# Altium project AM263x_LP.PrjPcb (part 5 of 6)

## Sheet PROC111_XDS110_2.SchDoc: XDS110 JTAG/USB-to-UART Bridge
size 431 x 279 mm; Date: Not shown in title block; ApprovedBy: Not shown in title block; CheckedBy: Not shown in title block; Author: Not shown in title block; CompanyName: Not shown in title block; Engineer: Not shown in title block; Organization: Not shown in title block; Address1: Not shown in title block; Address2: Not shown in title block; Address3: Not shown in title block; Address4: Not shown in title block; DocumentNumber: 22; Revision: Use project parameter SCH_Rev; SheetNumber: 22; SheetTotal: 24; PageSetup: Record=PageOptions¦CenterHorizontal=True¦CenterVertical=True¦PrintScale=1.00¦XCorrection=1.00¦YCorrection=1.00¦PrintKind=0¦BorderSize=5000000¦LeftOffset=0¦BottomOffset=0¦Orientation=2¦PaperLength=1000¦PaperWidth=1000¦Scale=100¦PaperSource=15¦PrintQuality=600¦MediaType=1¦DitherType=10¦PaperKind=Letter¦PrintScaleMode=1
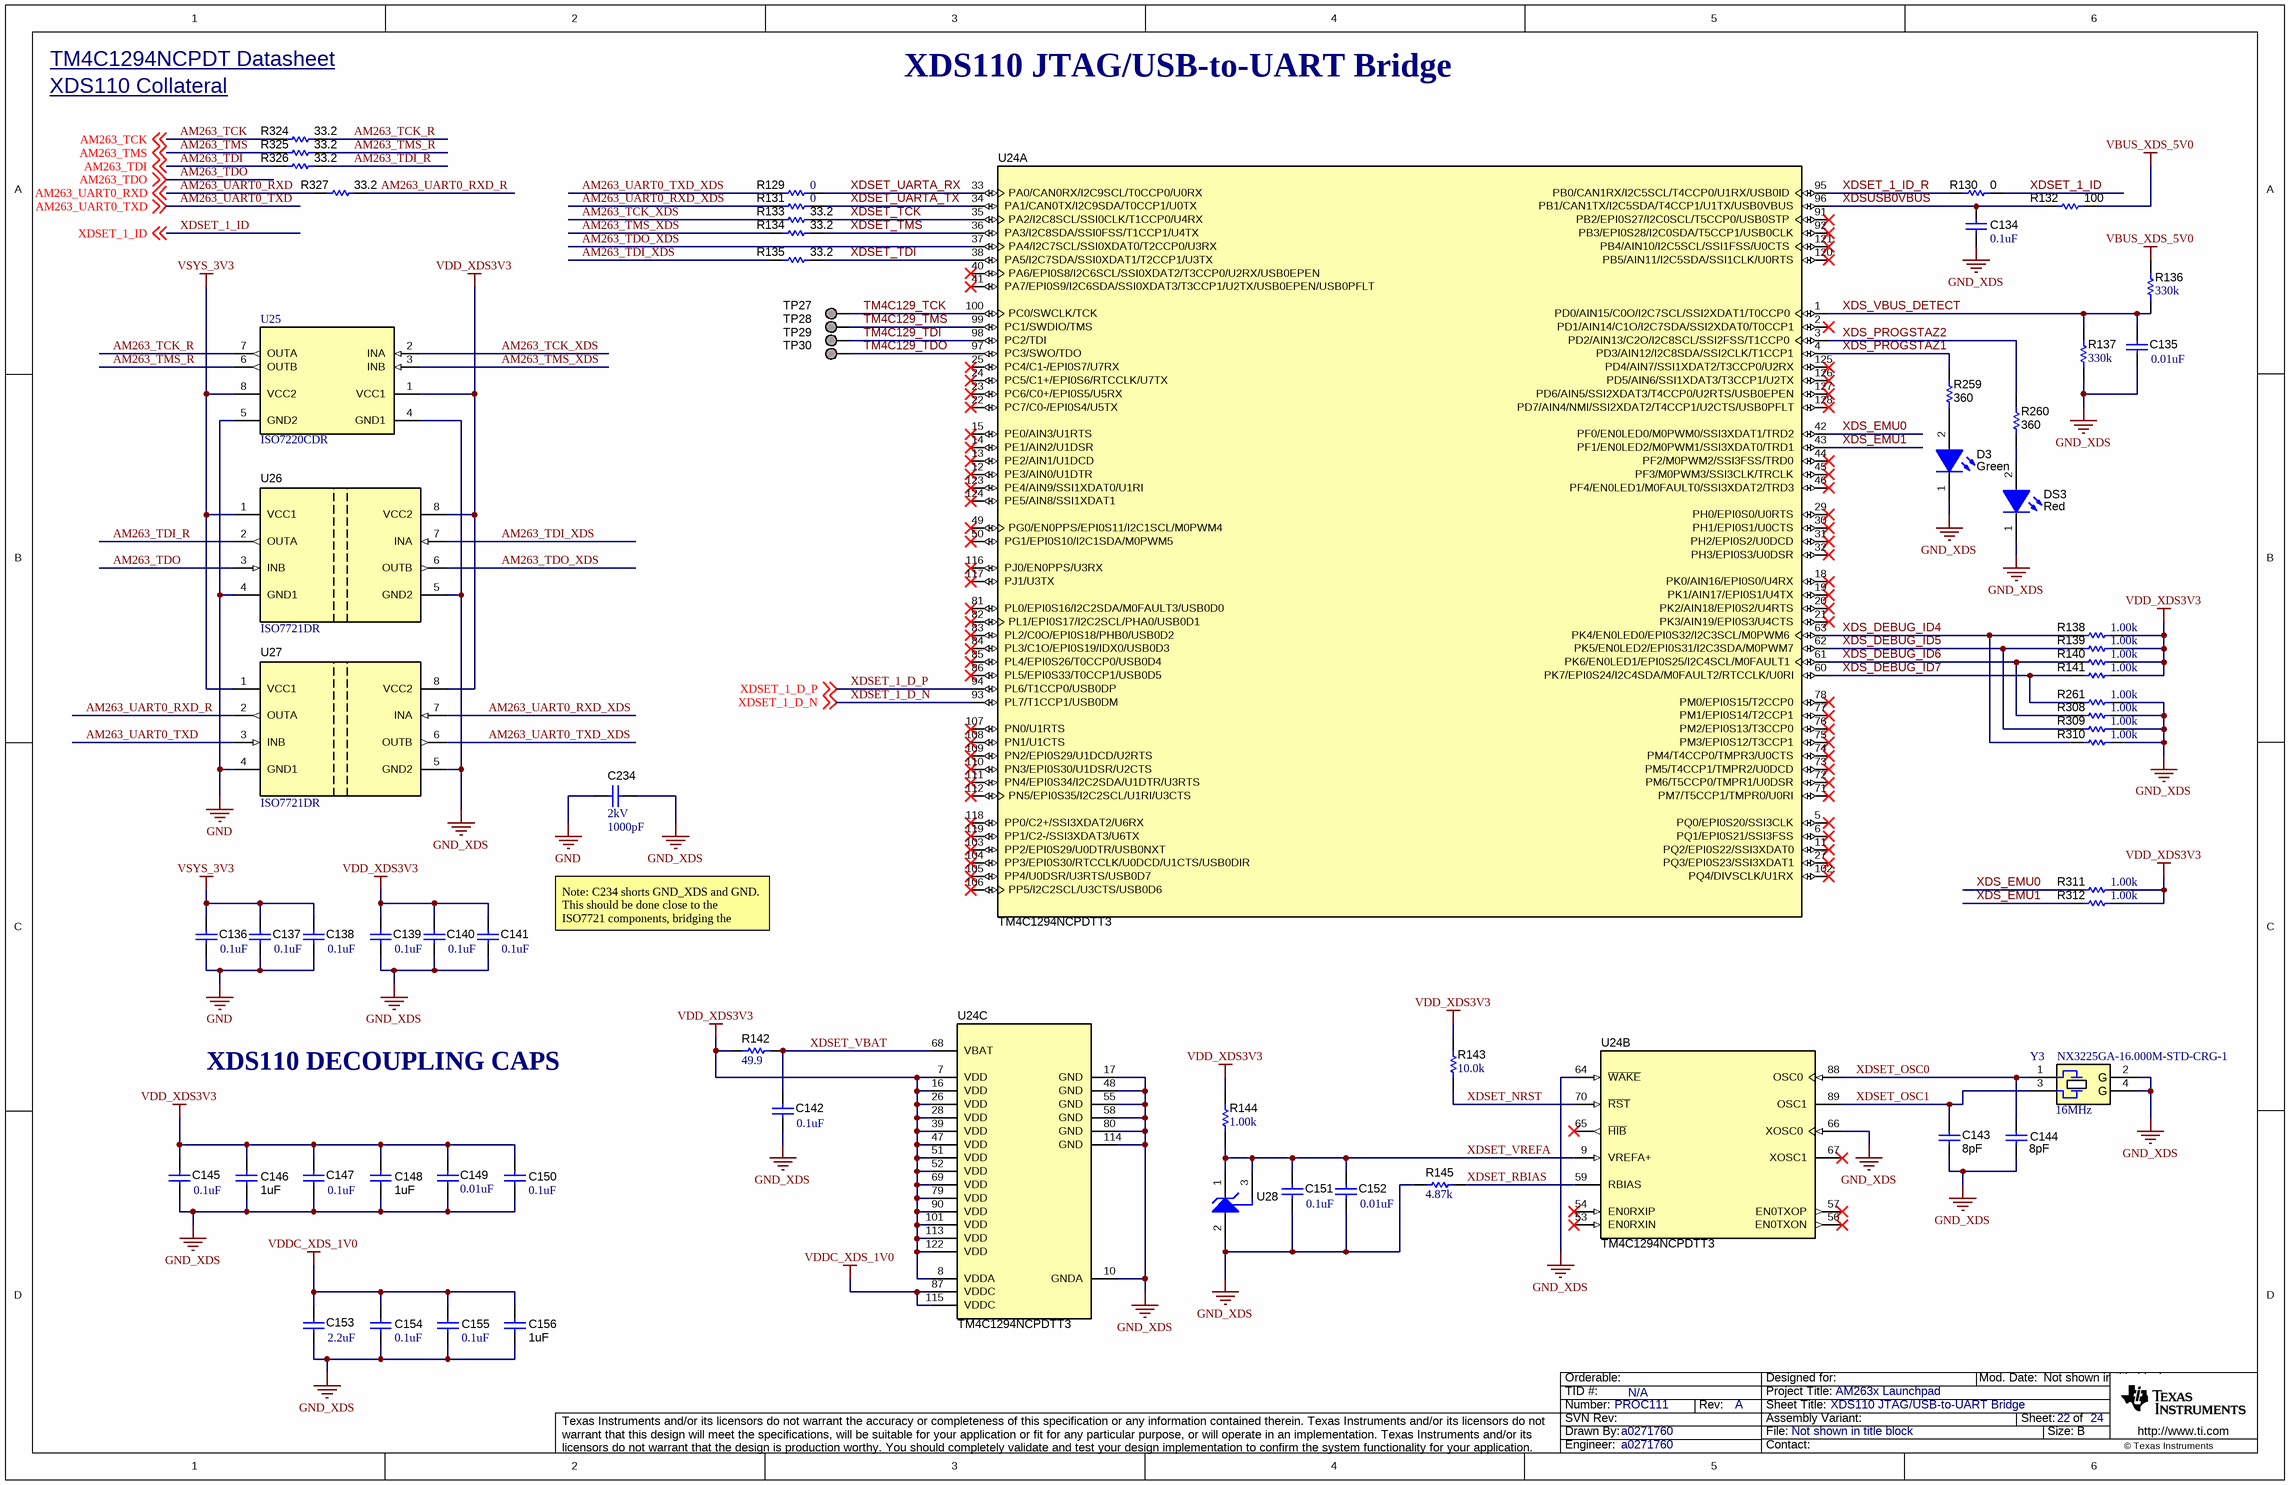
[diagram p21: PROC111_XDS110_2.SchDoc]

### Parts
C134  ValueDisplayed: 0.1uF  [0402]  (hidden comment: GRM155R71E104KE14D)
C135  ValueDisplayed: 0.01uF  [0402]  (hidden comment: GRM155R71E103KA01D)
C136  ValueDisplayed: 0.1uF  [0402]  (hidden comment: GRM155R71E104KE14D)
C137  ValueDisplayed: 0.1uF  [0402]  (hidden comment: GRM155R71E104KE14D)
C138  ValueDisplayed: 0.1uF  [0402]  (hidden comment: GRM155R71E104KE14D)
C139  ValueDisplayed: 0.1uF  [0402]  (hidden comment: GRM155R71E104KE14D)
C140  ValueDisplayed: 0.1uF  [0402]  (hidden comment: GRM155R71E104KE14D)
C141  ValueDisplayed: 0.1uF  [0402]  (hidden comment: GRM155R71E104KE14D)
C142  ValueDisplayed: 0.1uF  [0402]  (hidden comment: GRM155R71E104KE14D)
C143  Cap_F: 8pF  [0402]  (hidden comment: GCM1555C1H8R0DA16D)
C144  Cap_F: 8pF  [0402]  (hidden comment: GCM1555C1H8R0DA16D)
C145  ValueDisplayed: 0.1uF  [0402]  (hidden comment: GRM155R71E104KE14D)
C146  ValueDisplayed: 1uF  [0402_070]  (hidden comment: GCM155C71A105KE38D)
C147  ValueDisplayed: 0.1uF  [0402]  (hidden comment: GRM155R71E104KE14D)
C148  ValueDisplayed: 1uF  [0402_070]  (hidden comment: GCM155C71A105KE38D)
C149  ValueDisplayed: 0.01uF  [0402]  (hidden comment: GRM155R71E103KA01D)
C150  ValueDisplayed: 0.1uF  [0402]  (hidden comment: GRM155R71E104KE14D)
C151  ValueDisplayed: 0.1uF  [0402]  (hidden comment: GRM155R71E104KE14D)
C152  ValueDisplayed: 0.01uF  [0402]  (hidden comment: GRM155R71E103KA01D)
C153  ValueDisplayed: 2.2uF  [0402]  (hidden comment: GRM155C81C225KE11D)
C154  ValueDisplayed: 0.1uF  [0402]  (hidden comment: GRM155R71E104KE14D)
C155  ValueDisplayed: 0.1uF  [0402]  (hidden comment: GRM155R71E104KE14D)
C156  ValueDisplayed: 1uF  [0402_070]  (hidden comment: GCM155C71A105KE38D)
C234  VDC_V: 2kV  ValueDisplayed: 1000pF  [1808]  (hidden comment: GR442QR73D102KW01L)
D3  value Green  [WL-SMCW_GREEN]  (hidden comment: 150060VS75000)
DS3  value Red  [WL-SMCW_RED]  (hidden comment: 150060RS75000)
R129  ValueDisplayed: 0  [0402]  (hidden comment: ERJ-2GE0R00X)
R130  ValueDisplayed: 0  [0402L]  (hidden comment: ERJ-2GE0R00X)
R131  ValueDisplayed: 0  [0402]  (hidden comment: ERJ-2GE0R00X)
R132  ValueDisplayed: 100  [0402L]  (hidden comment: ERJ-2GEJ101X)
R133  ValueDisplayed: 33.2  [0402]  (hidden comment: CRCW040233R2FKED)
R134  ValueDisplayed: 33.2  [0402]  (hidden comment: CRCW040233R2FKED)
R135  ValueDisplayed: 33.2  [0402]  (hidden comment: CRCW040233R2FKED)
R136  ValueDisplayed: 330k  [0402L]  (hidden comment: CRCW0402330KFKED)
R137  ValueDisplayed: 330k  [0402L]  (hidden comment: CRCW0402330KFKED)
R138  ValueDisplayed: 1.00k  [0402L]  (hidden comment: CRCW04021K00FKED)
R139  ValueDisplayed: 1.00k  [0402L]  (hidden comment: CRCW04021K00FKED)
R140  ValueDisplayed: 1.00k  [0402L]  (hidden comment: CRCW04021K00FKED)
R141  ValueDisplayed: 1.00k  [0402L]  (hidden comment: CRCW04021K00FKED)
R142  ValueDisplayed: 49.9  [0402L]  (hidden comment: CRCW040249R9FKED)
R143  ValueDisplayed: 10.0k  [0402L]  (hidden comment: CRCW040210K0FKED)
R144  ValueDisplayed: 1.00k  [0402L]  (hidden comment: CRCW04021K00FKED)
R145  ValueDisplayed: 4.87k  [0402L]  (hidden comment: CRCW04024K87FKED)
R259  ValueDisplayed: 360  [0402L]  (hidden comment: ERJ-2GEJ361X)
R260  ValueDisplayed: 360  [0402L]  (hidden comment: ERJ-2GEJ361X)
R261  ValueDisplayed: 1.00k  [0402L]  (hidden comment: CRCW04021K00FKED)
R308  ValueDisplayed: 1.00k  [0402L]  (hidden comment: CRCW04021K00FKED)
R309  ValueDisplayed: 1.00k  [0402L]  (hidden comment: CRCW04021K00FKED)
R310  ValueDisplayed: 1.00k  [0402L]  (hidden comment: CRCW04021K00FKED)
R311  ValueDisplayed: 1.00k  [0402L]  (hidden comment: CRCW04021K00FKED)
R312  ValueDisplayed: 1.00k  [0402L]  (hidden comment: CRCW04021K00FKED)
R324  ValueDisplayed: 33.2  [0402]  (hidden comment: CRCW040233R2FKED)
R325  ValueDisplayed: 33.2  [0402]  (hidden comment: CRCW040233R2FKED)
R326  ValueDisplayed: 33.2  [0402]  (hidden comment: CRCW040233R2FKED)
R327  ValueDisplayed: 33.2  [0402]  (hidden comment: CRCW040233R2FKED)
TP27  TESTPOINT  [TP_25MIL-SMT]  (value not drawn)  (no BOM)
TP28  TESTPOINT  [TP_25MIL-SMT]  (value not drawn)  (no BOM)
TP29  TESTPOINT  [TP_25MIL-SMT]  (value not drawn)  (no BOM)
TP30  TESTPOINT  [TP_25MIL-SMT]  (value not drawn)  (no BOM)
U24  TM4C1294NCPDTT3  [PDT0128A]  (parts A,B,C of 3)
U25  ISO7220CDR  [D0008B_N]
U26  ISO7721DR  [D0008B_HV]
U27  ISO7721DR  [D0008B_HV]
U28  LM4040C25QDBZR  [DBZ0003A_N]  (value not drawn)
Y3  NX3225GA-16.000M-STD-CRG-1  Frequency_Fixed: 16MHz  [NDK_NX3225GA]

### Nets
GND: C136.1 C137.1 C138.1 C234.2 U25.5(GND2) U26.4(GND1) U27.4(GND1)
GND_XDS: C134.1 C135.1 C139.1 C140.1 C141.1 C142.2 C143.1 C144.1 C145.1 C146.2 C147.1 C148.2 C149.2 C150.1 C151.1 C152.1 C153.1 C154.1 C155.1 C156.2 C234.1 D3.1(K) DS3.1(K) R137.1 R145.1 R261.2 R308.2 R309.2 R310.2 U24.10(GNDA) U24.17(GND) U24.48(GND) U24.55(GND) U24.58(GND) U24.64(~{WAKE}) U24.66(XOSC0) U24.80(GND) U24.114(GND) U25.4(GND1) U26.5(GND2) U27.5(GND2) U28.2(ANODE) Y3.2(GND) Y3.4(GND)
VBUS_XDS_5V0: R132.2 R136.2
VDD_XDS3V3: C139.2 C140.2 C141.2 C145.2 C146.1 C147.2 C148.1 C149.1 C150.2 R138.2 R139.2 R140.2 R141.2 R142.2 R143.2 R144.2 R311.2 R312.2 U24.7(VDD) U24.8(VDDA) U24.16(VDD) U24.26(VDD) U24.28(VDD) U24.39(VDD) U24.47(VDD) U24.51(VDD) U24.52(VDD) U24.69(VDD) U24.79(VDD) U24.90(VDD) U24.101(VDD) U24.113(VDD) U24.122(VDD) U25.1(VCC1) U26.8(VCC2) U27.8(VCC2)
VDDC_XDS_1V0: C153.2 C154.2 C155.2 C156.1 U24.87(VDDC) U24.115(VDDC)
VSYS_3V3: C136.2 C137.2 C138.2 U25.8(VCC2) U26.1(VCC1) U27.1(VCC1)
AM263_TCK: R324.1 ; off-sheet AM263_TCK
AM263_TCK_R: R324.2 U25.7(OUTA)
AM263_TCK_XDS: R133.1 U25.2(INA)
AM263_TDI: R326.1 ; off-sheet AM263_TDI
AM263_TDI_R: R326.2 U26.2(OUTA)
AM263_TDI_XDS: R135.1 U26.7(INA)
AM263_TDO: U26.3(INB) ; off-sheet AM263_TDO
AM263_TDO_XDS: U24.37(PA4/I2C7SCL/SSI0XDAT0/T2CCP0/U3RX) U26.6(OUTB)
AM263_TMS: R325.1 ; off-sheet AM263_TMS
AM263_TMS_R: R325.2 U25.6(OUTB)
AM263_TMS_XDS: R134.1 U25.3(INB)
AM263_UART0_RXD: R327.1 ; off-sheet AM263_UART0_RXD
AM263_UART0_RXD_R: R327.2 U27.2(OUTA)
AM263_UART0_RXD_XDS: R131.1 U27.7(INA)
AM263_UART0_TXD: U27.3(INB) ; off-sheet AM263_UART0_TXD
AM263_UART0_TXD_XDS: R129.1 U27.6(OUTB)
TM4C129_TCK: TP27.1 U24.100(PC0/SWCLK/TCK)
TM4C129_TDI: TP29.1 U24.98(PC2/TDI)
TM4C129_TDO: TP30.1 U24.97(PC3/SWO/TDO)
TM4C129_TMS: TP28.1 U24.99(PC1/SWDIO/TMS)
XDS_DEBUG_ID4: R138.1 R310.1 U24.63(PK4/EN0LED0/EPI0S32/I2C3SCL/M0PWM6)
XDS_DEBUG_ID5: R139.1 R309.1 U24.62(PK5/EN0LED2/EPI0S31/I2C3SDA/M0PWM7)
XDS_DEBUG_ID6: R140.1 R308.1 U24.61(PK6/EN0LED1/EPI0S25/I2C4SCL/M0FAULT1)
XDS_DEBUG_ID7: R141.1 R261.1 U24.60(PK7/EPI0S24/I2C4SDA/M0FAULT2/RTCCLK/U0RI)
XDS_EMU0: R311.1 U24.42(PF0/EN0LED0/M0PWM0/SSI3XDAT1/TRD2)
XDS_EMU1: R312.1 U24.43(PF1/EN0LED2/M0PWM1/SSI3XDAT0/TRD1)
XDS_PROGSTAZ1: R259.2 U24.4(PD3/AIN12/I2C8SDA/SSI2CLK/T1CCP1)
XDS_PROGSTAZ2: R260.2 U24.3(PD2/AIN13/C2O/I2C8SCL/SSI2FSS/T1CCP0)
XDS_VBUS_DETECT: C135.2 R136.1 R137.2 U24.1(PD0/AIN15/C0O/I2C7SCL/SSI2XDAT1/T0CCP0)
XDSET_1_D_N: U24.93(PL7/T1CCP1/USB0DM) ; off-sheet XDSET_1_D_N
XDSET_1_D_P: U24.94(PL6/T1CCP0/USB0DP) ; off-sheet XDSET_1_D_P
XDSET_1_ID: R130.1 ; off-sheet XDSET_1_ID
XDSET_1_ID_R: R130.2 U24.95(PB0/CAN1RX/I2C5SCL/T4CCP0/U1RX/USB0ID)
XDSET_NRST: R143.1 U24.70(~{RST})
XDSET_OSC0: C144.2 U24.88(OSC0) Y3.1
XDSET_OSC1: C143.2 U24.89(OSC1) Y3.3
XDSET_RBIAS: R145.2 U24.59(RBIAS)
XDSET_TCK: R133.2 U24.35(PA2/I2C8SCL/SSI0CLK/T1CCP0/U4RX)
XDSET_TDI: R135.2 U24.38(PA5/I2C7SDA/SSI0XDAT1/T2CCP1/U3TX)
XDSET_TMS: R134.2 U24.36(PA3/I2C8SDA/SSI0FSS/T1CCP1/U4TX)
XDSET_UARTA_RX: R129.2 U24.33(PA0/CAN0RX/I2C9SCL/T0CCP0/U0RX)
XDSET_UARTA_TX: R131.2 U24.34(PA1/CAN0TX/I2C9SDA/T0CCP1/U0TX)
XDSET_VBAT: C142.1 R142.1 U24.68(VBAT)
XDSET_VREFA: C151.2 C152.2 R144.1 U24.9(VREFA+) U28.1(CATHODE) U28.3(NC)
XDSUSB0VBUS: C134.2 R132.1 U24.96(PB1/CAN1TX/I2C5SDA/T4CCP1/U1TX/USB0VBUS)
NetD3_2: D3.2(A) R259.1
NetDS3_2: DS3.2(A) R260.1

Not connected (* = marked no-connect by the designer): U24 2(PD1/AIN14/C1O/I2C7SDA/SSI2XDAT0/T0CCP1)* 5(PQ0/EPI0S20/SSI3CLK)* 6(PQ1/EPI0S21/SSI3FSS)* 11(PQ2/EPI0S22/SSI3XDAT0)* 12(PE3/AIN0/U1DTR)* 13(PE2/AIN1/U1DCD)* 14(PE1/AIN2/U1DSR)* 15(PE0/AIN3/U1RTS)* 18(PK0/AIN16/EPI0S0/U4RX)* 19(PK1/AIN17/EPI0S1/U4TX)* 20(PK2/AIN18/EPI0S2/U4RTS)* 21(PK3/AIN19/EPI0S3/U4CTS)* 22(PC7/C0-/EPI0S4/U5TX)* 23(PC6/C0+/EPI0S5/U5RX)* 24(PC5/C1+/EPI0S6/RTCCLK/U7TX)* 25(PC4/C1-/EPI0S7/U7RX)* 27(PQ3/EPI0S23/SSI3XDAT1)* 29(PH0/EPI0S0/U0RTS)* 30(PH1/EPI0S1/U0CTS)* 31(PH2/EPI0S2/U0DCD)* 32(PH3/EPI0S3/U0DSR)* 40(PA6/EPI0S8/I2C6SCL/SSI0XDAT2/T3CCP0/U2RX/USB0EPEN)* 41(PA7/EPI0S9/I2C6SDA/SSI0XDAT3/T3CCP1/U2TX/USB0EPEN/USB0PFLT)* 44(PF2/M0PWM2/SSI3FSS/TRD0)* 45(PF3/M0PWM3/SSI3CLK/TRCLK)* 46(PF4/EN0LED1/M0FAULT0/SSI3XDAT2/TRD3)* 49(PG0/EN0PPS/EPI0S11/I2C1SCL/M0PWM4)* 50(PG1/EPI0S10/I2C1SDA/M0PWM5)* 53(EN0RXIN)* 54(EN0RXIP)* 56(EN0TXON)* 57(EN0TXOP)* 65(~{HIB})* 67(XOSC1)* 71(PM7/T5CCP1/TMPR0/U0RI)* 72(PM6/T5CCP0/TMPR1/U0DSR)* 73(PM5/T4CCP1/TMPR2/U0DCD)* 74(PM4/T4CCP0/TMPR3/U0CTS)* 75(PM3/EPI0S12/T3CCP1)* 76(PM2/EPI0S13/T3CCP0)* 77(PM1/EPI0S14/T2CCP1)* 78(PM0/EPI0S15/T2CCP0)* 81(PL0/EPI0S16/I2C2SDA/M0FAULT3/USB0D0)* 82(PL1/EPI0S17/I2C2SCL/PHA0/USB0D1)* 83(PL2/C0O/EPI0S18/PHB0/USB0D2)* 84(PL3/C1O/EPI0S19/IDX0/USB0D3)* 85(PL4/EPI0S26/T0CCP0/USB0D4)* 86(PL5/EPI0S33/T0CCP1/USB0D5)* 91(PB2/EPI0S27/I2C0SCL/T5CCP0/USB0STP)* 92(PB3/EPI0S28/I2C0SDA/T5CCP1/USB0CLK)* 102(PQ4/DIVSCLK/U1RX)* 103(PP2/EPI0S29/U0DTR/USB0NXT)* 104(PP3/EPI0S30/RTCCLK/U0DCD/U1CTS/USB0DIR)* 105(PP4/U0DSR/U3RTS/USB0D7)* 106(PP5/I2C2SCL/U3CTS/USB0D6)* 107(PN0/U1RTS)* 108(PN1/U1CTS)* 109(PN2/EPI0S29/U1DCD/U2RTS)* 110(PN3/EPI0S30/U1DSR/U2CTS)* 111(PN4/EPI0S34/I2C2SDA/U1DTR/U3RTS)* 112(PN5/EPI0S35/I2C2SCL/U1RI/U3CTS)* 116(PJ0/EN0PPS/U3RX)* 117(PJ1/U3TX)* 118(PP0/C2+/SSI3XDAT2/U6RX)* 119(PP1/C2-/SSI3XDAT3/U6TX)* 120(PB5/AIN11/I2C5SDA/SSI1CLK/U0RTS)* 121(PB4/AIN10/I2C5SCL/SSI1FSS/U0CTS)* 123(PE4/AIN9/SSI1XDAT0/U1RI)* 124(PE5/AIN8/SSI1XDAT1)* 125(PD4/AIN7/SSI1XDAT2/T3CCP0/U2RX)* 126(PD5/AIN6/SSI1XDAT3/T3CCP1/U2TX)* 127(PD6/AIN5/SSI2XDAT3/T4CCP0/U2RTS/USB0EPEN)* 128(PD7/AIN4/NMI/SSI2XDAT2/T4CCP1/U2CTS/USB0PFLT)*

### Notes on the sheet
- XDS110 Collateral <https://software-dl.ti.com/ccs/esd/documents/xdsdebugprobes/emu_xds110.html>
- TM4C1294NCPDT Datasheet <http://www.ti.com/lit/ds/symlink/tm4c1294ncpdt.pdf>
- XDS110 JTAG/USB-to-UART Bridge
- Note: C234 shorts GND_XDS and GND. This should be done close to the ISO7721 components, bridging the air-gap between the two portions of the PCB
- XDS110 DECOUPLING CAPS

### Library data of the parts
C134 C136-C142 C145 C147 C150 C151 C154 C155 = CMP-0006659-2: CAP, CERM, 0.1 uF, 25 V, +/- 10%, X7R, 0402; Manufacturer: MuRata; TaMin_C: -55°C; Polarized: N; SizeAreaWB_mm2: 3; U/M: EA; Value: 0.1uF; TaMax_C: 125°C; SizeZ_mm: 0.6; SizeX_mm: 1; SizeY_mm: 0.5; Value2: 25V; Cap_F: 100nF; AEC Category: Q200; Value1: Unknown
C135 C149 C152 = CMP-0006658-2: CAP, CERM, 0.01 uF, 25 V, +/- 10%, X7R, 0402; Manufacturer: MuRata; TaMin_C: -55°C; Polarized: N; SizeAreaWB_mm2: 3; U/M: EA; Value: 0.01uF; TaMax_C: 125°C; SizeZ_mm: 0.6; SizeX_mm: 1; SizeY_mm: 0.5; Value2: 25V; Cap_F: 10nF; AEC Category: Q200; Value1: Unknown
C143 C144 = CMP-0087060-3: Cap Ceramic 8pF 50V C0G 0.5pF SMD 0402 125C Paper T/R; Manufacturer: Murata Electronics North America; TempCo: 30ppm/°C; AEC Qualified: Yes; AEC Grade: Grade 1; SizeZ_mm: 0.55mm
C146 C148 C156 = CMP-0006349-2: CAP, CERM, 1 uF, 10 V, +/- 10%, X7S, AEC-Q200 Grade 1, 0402; Manufacturer: MuRata; TaMin_C: -55°C; Polarized: N; SizeAreaWB_mm2: 3; Value1: Unknown; U/M: EA; Value: 1uF; TaMax_C: 125°C; SizeZ_mm: 0.7; SizeX_mm: 1; SizeY_mm: 0.5; Cap_Case: 0402; Value2: 10V; AEC Qualified: Y; Cap_F: 1µF; AEC Category: Q200
C153 = CMP-0006526-2: CAP, CERM, 2.2 uF, 16 V, +/- 10%, X6S, 0402; Manufacturer: MuRata; TaMin_C: -55°C; Polarized: N; SizeAreaWB_mm2: 3; Value1: Unknown; U/M: EA; Value: 2.2uF; TaMax_C: 105°C; SizeZ_mm: 0.6; SizeX_mm: 1; SizeY_mm: 0.5; Value2: 16V; Cap_F: 2.2µF; AEC Category: Q200
C234 = CMP-0009436-2: CAP, CERM, 1000 pF, 2000 V, +/- 10%, X7R, 1808; Manufacturer: MuRata; TaMin_C: -55°C; Polarized: N; SizeAreaWB_mm2: 16.5; Value1: Unknown; U/M: EA; Value: 1000pF; TaMax_C: 125°C; SizeZ_mm: 2.03; SizeX_mm: 4.5; SizeY_mm: 2; Value2: 2000V; SizeArea_mm2: 9; Cap_F: 1nF; AEC Category: Q200
D3 = CMP-0002894-2: LED, Green, SMD; Manufacturer: Wurth Elektronik; Io_A: 20mA; Value1: W; Vf_V: 2V; Type: AlInGaP
DS3 = CMP-0002947-3: LED, Red, SMD; Manufacturer: Wurth Elektronik; Value1: 0.072W; Vf_V: 2V; Angle: 140; Tjmax_C: 85°C; Type: AlInGaP; Vr_V: 5V; Io_A: 30mA; Power_TotalModule: 72mW
R129 R131 = CMP-0026992-3: RES, 0, 5%, 0.1 W, AEC-Q200 Grade 0, 0402; Manufacturer: Panasonic; Power_W: 100mW; TempCo: 600 ppm/C; Value_Code: 0000; Value: 0; EIA_Code: E24; SizeX_mm: 1; SizeY_mm: 0.5; SizeZ_mm: 0.6; Value2: 0.1W; CompType: Resistor; AEC Qualified: Y; VDC_V: 50V; AEC Category: Q200; SizeAreaWB_mm2: 3; INSTALLATION: DNP
R130 = CMP-0026992-3: RES, 0, 5%, 0.1 W, AEC-Q200 Grade 0, 0402; Manufacturer: Panasonic; Power_W: 100mW; TempCo: 600 ppm/C; Value_Code: 0000; Value: 0; EIA_Code: E24; SizeX_mm: 1; SizeY_mm: 0.5; SizeZ_mm: 0.6; Value2: 0.1W; AEC Qualified: Y; VDC_V: 50V; AEC Category: Q200; SizeAreaWB_mm2: 3
R132 = CMP-0026993-2: RES, 100, 5%, 0.1 W, AEC-Q200 Grade 0, 0402; Manufacturer: Panasonic; Power_W: 100mW; TempCo: 200 ppm/C; Value_Code: 100R; U/M: EA; Value: 100; EIA_Code: E24; SizeX_mm: 1; SizeY_mm: 0.5; SizeZ_mm: 0.6; Value2: 0.1W; AEC Qualified: Y; AEC Grade: 0; AEC Category: Q200
R133-R135 R324-R327 = CMP-0026299-2: RES, 33.2, 1%, 0.063 W, AEC-Q200 Grade 0, 0402; Manufacturer: Vishay-Dale; Power_W: 63mW; TempCo: 100 ppm/C; Value_Code: 33R2; Value: 33.2; EIA_Code: E96; SizeX_mm: 1; SizeY_mm: 0.5; SizeZ_mm: 0.6; Value2: 0.063W; AEC Qualified: Y; VDC_V: 50V; AEC Category: Q200; AEC Grade: 0
R136 R137 = CMP-0078210-2: RES, 330 k, 1%, 0.063 W, AEC-Q200 Grade 0, 0402; Manufacturer: Vishay-Dale; SizeArea_mm2: 0.5; AEC Qualified: Y; AEC Category: Q200; Value: 330k; SizeZ_mm: 0.6; TempCo: 100 ppm/C; AEC Grade: 0; Power_W: 63mW; VDC_V: 50V; Value2: 0.063W; SizeX_mm: 1
R138-R141 R144 R261 R308-R312 = CMP-0026071-3: RES, 1.00 k, 1%, 0.063 W, AEC-Q200 Grade 0, 0402; Manufacturer: Vishay-Dale; Power_W: 63mW; TempCo: 100 ppm/C; Value_Code: 1k00; Value: 1.00k; EIA_Code: E96; Res_ohm: 1k; SizeX_mm: 1; SizeY_mm: 0.5; SizeZ_mm: 0.6; Value2: 0.063W; AEC Qualified: Y; VDC_V: 50V; AEC Category: Q200; AEC Grade: 0
R142 = CMP-0026404-2: RES, 49.9, 1%, 0.063 W, AEC-Q200 Grade 0, 0402; Manufacturer: Vishay-Dale; Power_W: 63mW; TempCo: 100 ppm/C; Value_Code: 49R9; Value: 49.9; EIA_Code: E96; SizeX_mm: 1; SizeY_mm: 0.5; SizeZ_mm: 0.6; Value2: 0.063W; AEC Qualified: Y; VDC_V: 50V; AEC Category: Q200; AEC Grade: 0
R143 = CMP-0025958-3: RES, 10.0 k, 1%, 0.063 W, AEC-Q200 Grade 0, 0402; Manufacturer: Vishay-Dale; Power_W: 63mW; TempCo: 100 ppm/C; Value_Code: 10k0; Value: 10.0k; EIA_Code: E96; Res_ohm: 10k; SizeX_mm: 1; SizeY_mm: 0.5; SizeZ_mm: 0.6; Value2: 0.063W; AEC Qualified: Y; VDC_V: 50V; AEC Category: Q200; AEC Grade: 0
R145 = CMP-0026413-2: RES, 4.87 k, 1%, 0.063 W, AEC-Q200 Grade 0, 0402; Manufacturer: Vishay-Dale; Power_W: 63mW; TempCo: 100 ppm/C; Value_Code: 4k87; Value: 4.87k; EIA_Code: E96; SizeX_mm: 1; SizeY_mm: 0.5; SizeZ_mm: 0.6; Value2: 0.063W; AEC Qualified: Y; VDC_V: 50V; AEC Category: Q200; AEC Grade: 0
R259 R260 = CMP-0078194-1: RES, 360, 5%, 0.1 W, AEC-Q200 Grade 0, 0402; Manufacturer: Panasonic; Value_Code: 360R; SizeArea_mm2: 0.5; AEC Qualified: Y; AEC Category: Q200; Value: 360; SizeZ_mm: 0.6; EIA_Code: E24; TempCo: 200 ppm/C; AEC Grade: 0; Power_W: 100mW; VDC_V: 50V; Value2: 0.1W; U/M: EA; SizeX_mm: 1
TP27-TP30 = CMP-0078143-3: TEST POINT.  No entry in BOM.
U24 = CMP-0029856-2: Tiva C Series Microcontroller, 1024 KB Flash, 256 KB SRAM, 12 Bit, 20 Channels, -40 to 105 degC, 128-Pin TQFP (PDT), Green (RoHS & no Sb/Br), Tray; Manufacturer: Texas Instruments; ADC Channels: 20; CPU: ARM Cortex-M4; Flash: 1024 KB; ADC Resolution: 12 Bits; Max Speed: 120 MHz; SRAM: 256 KB; SizeAreaWB_mm2: 324.0; SizeArea_mm2: 256.0; SizeX_mm: 16.0; SizeZ_mm: 1.2; CompType: IC
U25 = CMP-0029369-1: 25 Mbps Dual Channels, 2 / 0, Digital Isolator, 3.3 V / 5 V, -40 to +125 degC, 8-pin SOIC (D), Green (RoHS & no Sb/Br); Manufacturer: Texas Instruments; Supply Voltage(s)(V): 3.3, 5; Prop Delay(Max)(ns): 42; Insulation Rating(VRMS): 2500; Datarate(Mbps): 25; TTL/CMOS Input Threshold: TTL; Rating: Catalog; Input Noise Filter: Yes
U26 U27 = CMP-0076059-2: High Speed, Robust EMC Dual-Channel Digital Isolator, D0008B (SOIC-8); Manufacturer: Texas Instruments; SizeY_mm: 4.9; SizeArea_mm2: 29.4; Rating: Catalog; CompType: IC; AEC Category: Q200; AEC Qualified: N; SizeZ_mm: 1.75; SizeAreaWB_mm2: 55.2; SizeX_mm: 6.0
U28 = CMP-0033001-1: Precision Micropower Shunt Voltage Reference, 0.5% accuracy, 2.5 V, 15 ppm / degC, 15 mA, -40 to 125 degC, 3-pin SOT-23 (DBZ), Green (RoHS & no Sb/Br); Manufacturer: Texas Instruments; Initial Accuracy @ 25/deg C(%): 0.5; Temp Coeff(Typ)(ppm/ degree C): 15; Temp Coeff(Max)(ppm/ degree C): 100; Rating: Catalog; Min Iz for Regulation(uA): 75; VO(V): 2.5
Y3 = CMP-0004635-3: Crystal, 16 MHz, 8pF, SMD; Manufacturer: NDK; TaMax_C: 70°C; TaMin_C: -10°C; Frequency Stability: +/-30ppm

## Sheet PROC111_LED.SchDoc
size 431 x 279 mm; Date: Not shown in title block; ApprovedBy: Not shown in title block; CheckedBy: Not shown in title block; Author: Not shown in title block; CompanyName: Not shown in title block; Engineer: Not shown in title block; Organization: Not shown in title block; Address1: Not shown in title block; Address2: Not shown in title block; Address3: Not shown in title block; Address4: Not shown in title block; DocumentNumber: 23; Revision: Use project parameter SCH_Rev; SheetNumber: 23; SheetTotal: 24; PageSetup: Record=PageOptions¦CenterHorizontal=True¦CenterVertical=True¦PrintScale=1.00¦XCorrection=1.00¦YCorrection=1.00¦PrintKind=0¦BorderSize=5000000¦LeftOffset=0¦BottomOffset=0¦Orientation=2¦PaperLength=1000¦PaperWidth=1000¦Scale=100¦PaperSource=15¦PrintQuality=600¦MediaType=1¦DitherType=10¦PaperKind=Letter¦PrintScaleMode=1
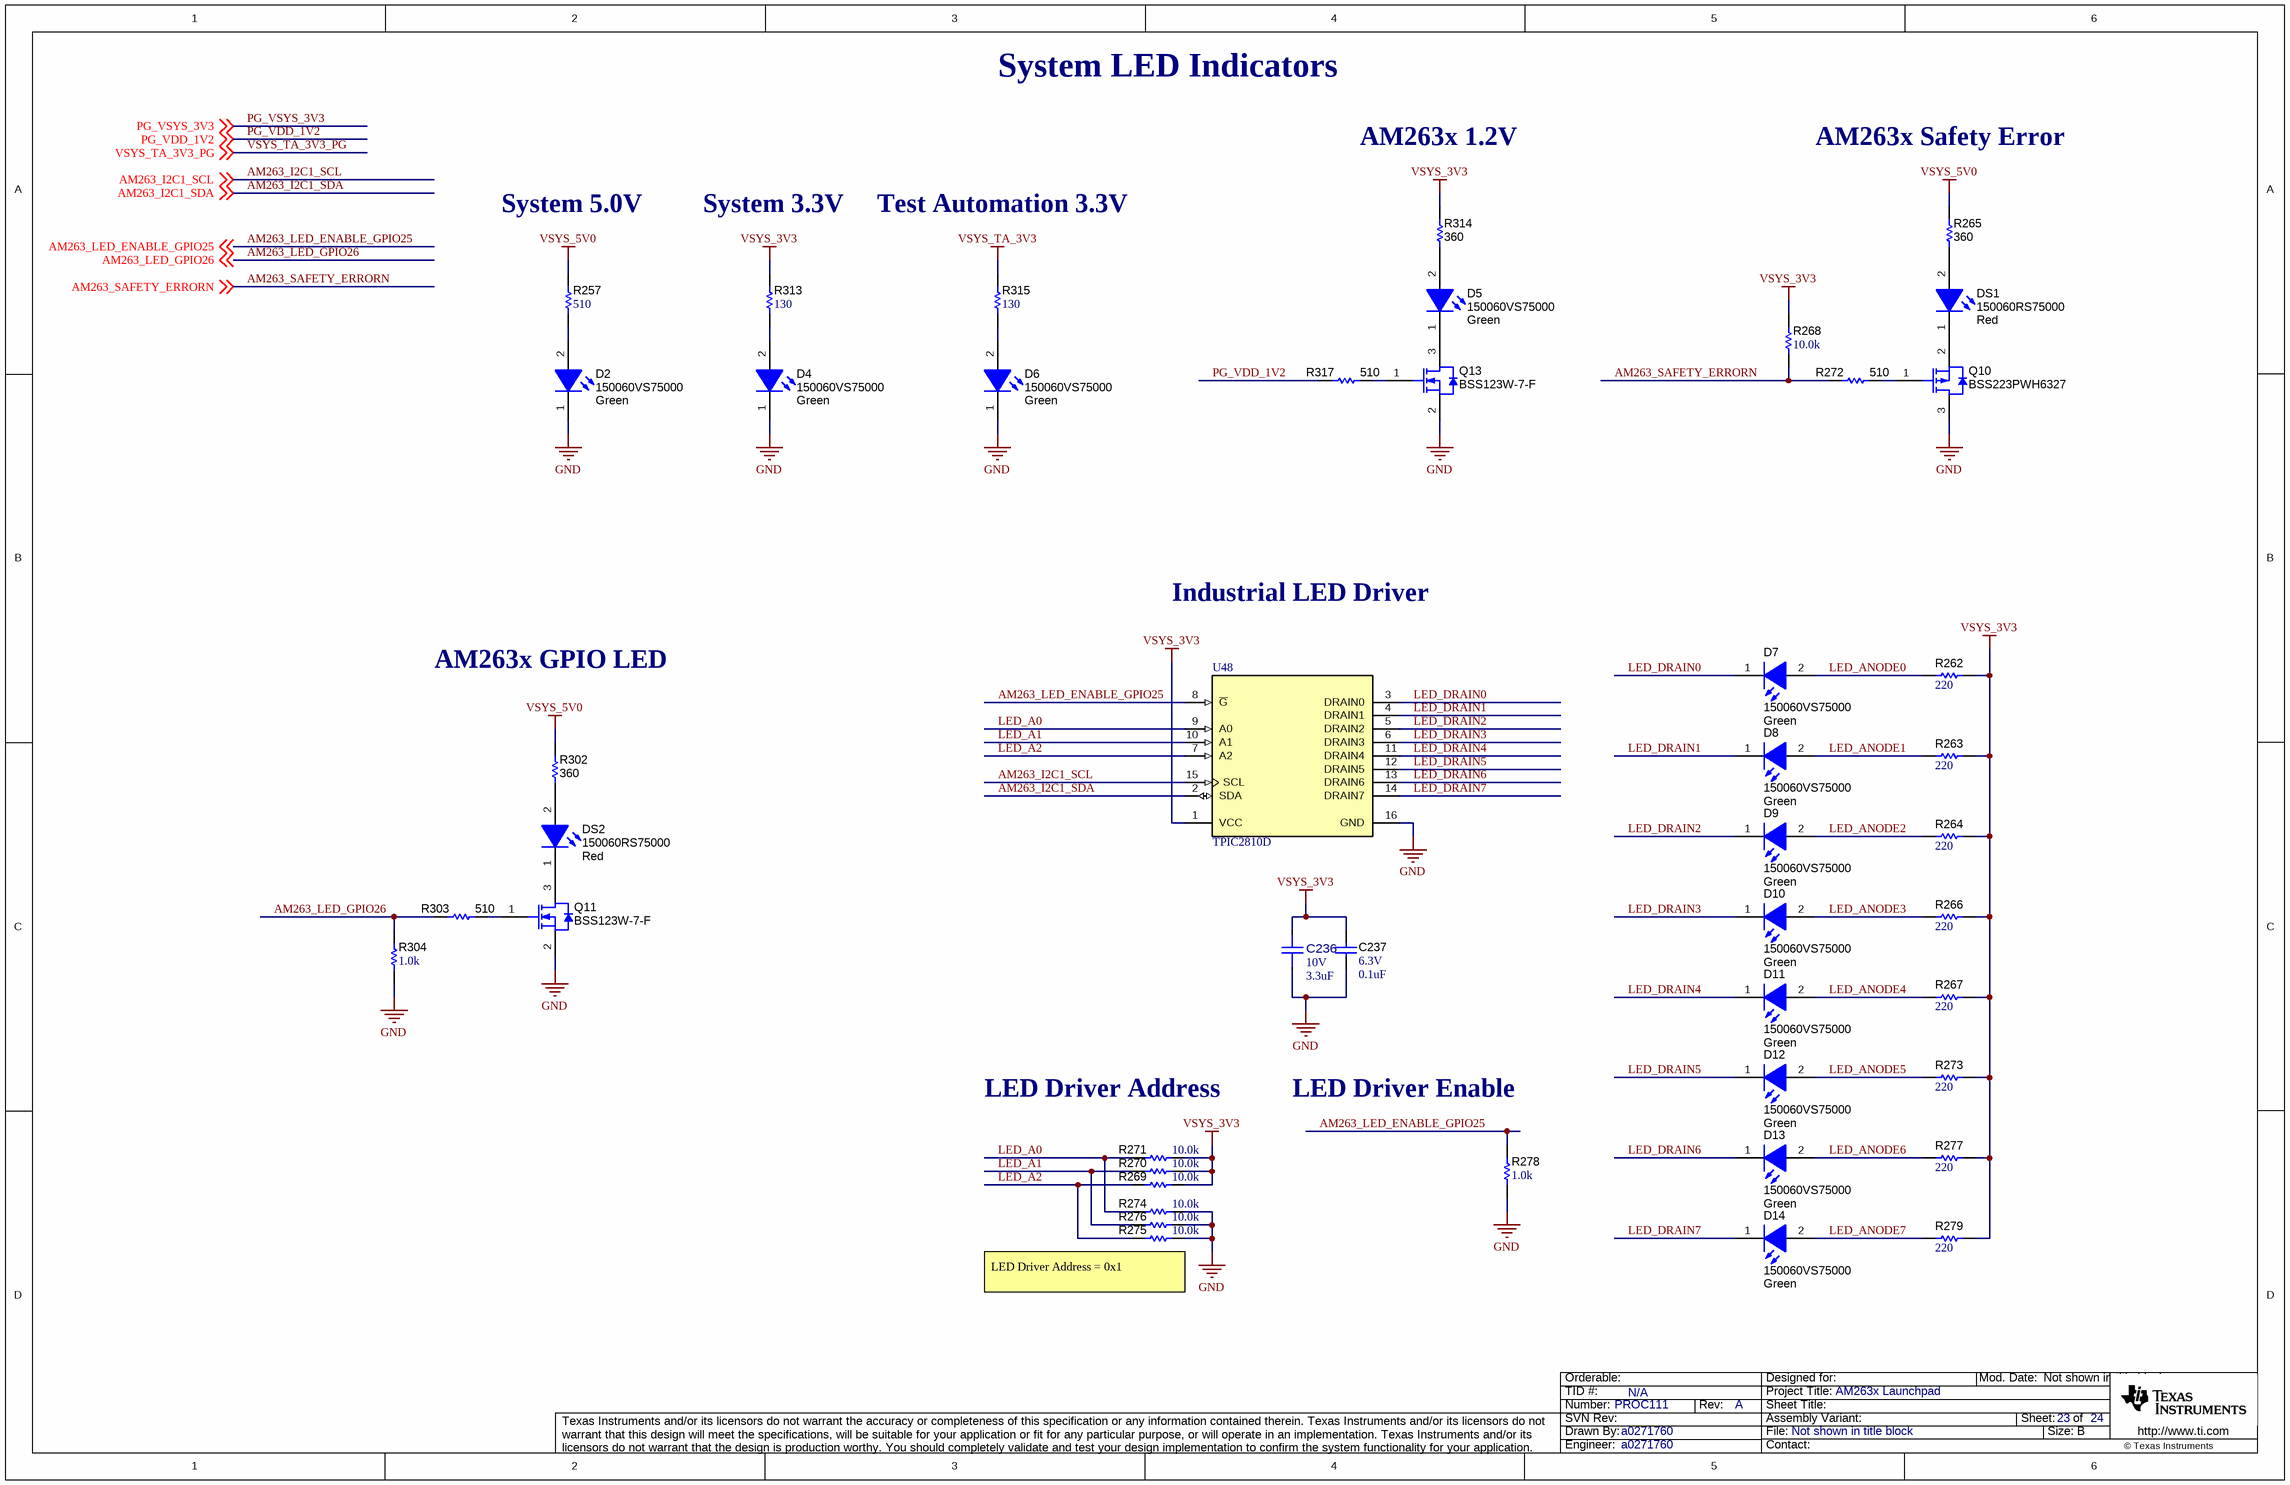
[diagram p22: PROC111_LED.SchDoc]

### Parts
C236  VDC_V: 10V  ValueDisplayed: 3.3uF  [FP-CL10A335KP8NNNC_0603-MFG]  (hidden comment: CL10A335KP8NNNC)
C237  VDC_V: 6.3V  ValueDisplayed: 0.1uF  [0402]  (hidden comment: GRM155R70J104KA01D)
D2  150060VS75000  value Green  [WL-SMCW_GREEN]
D4  150060VS75000  value Green  [WL-SMCW_GREEN]
D5  150060VS75000  value Green  [WL-SMCW_GREEN]
D6  150060VS75000  value Green  [WL-SMCW_GREEN]
D7  150060VS75000  value Green  [WL-SMCW_GREEN]
D8  150060VS75000  value Green  [WL-SMCW_GREEN]
D9  150060VS75000  value Green  [WL-SMCW_GREEN]
D10  150060VS75000  value Green  [WL-SMCW_GREEN]
D11  150060VS75000  value Green  [WL-SMCW_GREEN]
D12  150060VS75000  value Green  [WL-SMCW_GREEN]
D13  150060VS75000  value Green  [WL-SMCW_GREEN]
D14  150060VS75000  value Green  [WL-SMCW_GREEN]
DS1  150060RS75000  value Red  [WL-SMCW_RED]
DS2  150060RS75000  value Red  [WL-SMCW_RED]
Q10  BSS223PWH6327  [SOT-323]
Q11  BSS123W-7-F  [SOT-323]
Q13  BSS123W-7-F  [SOT-323]
R257  ValueDisplayed: 510  [0402]  (hidden comment: ERJ-2RKF5100X)
R262  ValueDisplayed: 220  [0402]  (hidden comment: ERJ-2RKF2200X)
R263  ValueDisplayed: 220  [0402]  (hidden comment: ERJ-2RKF2200X)
R264  ValueDisplayed: 220  [0402]  (hidden comment: ERJ-2RKF2200X)
R265  ValueDisplayed: 360  [0402L]  (hidden comment: ERJ-2GEJ361X)
R266  ValueDisplayed: 220  [0402]  (hidden comment: ERJ-2RKF2200X)
R267  ValueDisplayed: 220  [0402]  (hidden comment: ERJ-2RKF2200X)
R268  ValueDisplayed: 10.0k  [0402]  (hidden comment: ERJ-2RKF1002X)
R269  ValueDisplayed: 10.0k  [0402]  (hidden comment: ERJ-2RKF1002X)
R270  ValueDisplayed: 10.0k  [0402]  (hidden comment: ERJ-2RKF1002X)
R271  ValueDisplayed: 10.0k  [0402]  (hidden comment: ERJ-2RKF1002X)
R272  ValueDisplayed: 510  [0402L]  (hidden comment: ERJ-2GEJ511X)
R273  ValueDisplayed: 220  [0402]  (hidden comment: ERJ-2RKF2200X)
R274  ValueDisplayed: 10.0k  [0402]  (hidden comment: ERJ-2RKF1002X)
R275  ValueDisplayed: 10.0k  [0402]  (hidden comment: ERJ-2RKF1002X)
R276  ValueDisplayed: 10.0k  [0402]  (hidden comment: ERJ-2RKF1002X)
R277  ValueDisplayed: 220  [0402]  (hidden comment: ERJ-2RKF2200X)
R278  ValueDisplayed: 1.0k  [0402]  (hidden comment: ERJ-2GEJ102X)
R279  ValueDisplayed: 220  [0402]  (hidden comment: ERJ-2RKF2200X)
R302  ValueDisplayed: 360  [0402L]  (hidden comment: ERJ-2GEJ361X)
R303  ValueDisplayed: 510  [0402L]  (hidden comment: ERJ-2GEJ511X)
R304  ValueDisplayed: 1.0k  [0402]  (hidden comment: ERJ-2GEJ102X)
R313  ValueDisplayed: 130  [0402]  (hidden comment: CRCW0402130RFKED)
R314  ValueDisplayed: 360  [0402L]  (hidden comment: ERJ-2GEJ361X)
R315  ValueDisplayed: 130  [0402]  (hidden comment: CRCW0402130RFKED)
R317  ValueDisplayed: 510  [0402L]  (hidden comment: ERJ-2GEJ511X)
U48  TPIC2810D  [D0016A_N]

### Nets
GND: C236.1 C237.2 D2.1(K) D4.1(K) D6.1(K) Q10.3(D) Q11.2(S) Q13.2(S) R274.1 R275.1 R276.1 R278.1 R304.1 U48.16(GND)
VSYS_3V3: C236.2 C237.1 R262.2 R263.2 R264.2 R266.2 R267.2 R268.2 R269.1 R270.1 R271.1 R273.2 R277.2 R279.2 R313.2 R314.2 U48.1(VCC)
VSYS_5V0: R257.2 R265.2 R302.2
VSYS_TA_3V3: R315.2
AM263_I2C1_SCL: U48.15(SCL) ; off-sheet AM263_I2C1_SCL
AM263_I2C1_SDA: U48.2(SDA) ; off-sheet AM263_I2C1_SDA
AM263_LED_ENABLE_GPIO25: R278.2 U48.8(~{G}) ; off-sheet AM263_LED_ENABLE_GPIO25
AM263_LED_GPIO26: R303.1 R304.2 ; off-sheet AM263_LED_GPIO26
AM263_SAFETY_ERRORN: R268.1 R272.1 ; off-sheet AM263_SAFETY_ERRORN
LED_A0: R271.2 R274.2 U48.9(A0)
LED_A1: R270.2 R276.2 U48.10(A1)
LED_A2: R269.2 R275.2 U48.7(A2)
LED_ANODE0: D7.2(A) R262.1
LED_ANODE1: D8.2(A) R263.1
LED_ANODE2: D9.2(A) R264.1
LED_ANODE3: D10.2(A) R266.1
LED_ANODE4: D11.2(A) R267.1
LED_ANODE5: D12.2(A) R273.1
LED_ANODE6: D13.2(A) R277.1
LED_ANODE7: D14.2(A) R279.1
LED_DRAIN0: D7.1(K) U48.3(DRAIN0)
LED_DRAIN1: D8.1(K) U48.4(DRAIN1)
LED_DRAIN2: D9.1(K) U48.5(DRAIN2)
LED_DRAIN3: D10.1(K) U48.6(DRAIN3)
LED_DRAIN4: D11.1(K) U48.11(DRAIN4)
LED_DRAIN5: D12.1(K) U48.12(DRAIN5)
LED_DRAIN6: D13.1(K) U48.13(DRAIN6)
LED_DRAIN7: D14.1(K) U48.14(DRAIN7)
PG_VDD_1V2: R317.1 ; off-sheet PG_VDD_1V2
NetD2_2: D2.2(A) R257.1
NetD4_2: D4.2(A) R313.1
NetD5_1: D5.1(K) Q13.3(D)
NetD5_2: D5.2(A) R314.1
NetD6_2: D6.2(A) R315.1
NetDS1_1: DS1.1(K) Q10.2(S)
NetDS1_2: DS1.2(A) R265.1
NetDS2_1: DS2.1(K) Q11.3(D)
NetDS2_2: DS2.2(A) R302.1
NetQ10_1: Q10.1(G) R272.2
NetQ11_1: Q11.1(G) R303.2
NetQ13_1: Q13.1(G) R317.2

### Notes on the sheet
- System LED Indicators
- AM263x 1.2V
- AM263x Safety Error
- System 5.0V
- System 3.3V
- Test Automation 3.3V
- Industrial LED Driver
- AM263x GPIO LED
- LED Driver Address
- LED Driver Enable
- (near R275) LED Driver Address = 0x1

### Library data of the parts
C236 = CMP-0042976-1: Cap Ceramic 3.3uF 10V X5R ±10% Pad SMD 0603 +85°C T/R; Manufacturer: Samsung; TempCo: 15%; Value: 3.3µF; SizeZ_mm: 0.9mm; AEC Qualified: No
C237 = CMP-0006623-2: CAP, CERM, 0.1 uF, 6.3 V, +/- 10%, X7R, 0402; Manufacturer: MuRata; TaMin_C: -55°C; Polarized: N; SizeAreaWB_mm2: 3; Value1: Unknown; U/M: EA; Value: 0.1uF; TaMax_C: 125°C; SizeZ_mm: 0.6; SizeX_mm: 1; SizeY_mm: 0.5; Cap_F: 100nF; AEC Category: Q200
D2 D4-D14 = CMP-0002894-2: as D3 on sheet PROC111_XDS110_2
DS1 DS2 = CMP-0002947-3: as DS3 on sheet PROC111_XDS110_2
Q10 = CMP-0000010-3: MOSFET, P-CH, -20 V, -0.39 A, SOT-323; Alternate Manufacturer: None; Manufacturer: Infineon Technologies; Value: -20V; Rdson45_ohm: 1.2; SizeX_mm: 2.2; AEC Category: Q101; ChMode: Enhancement; Vgs_V: -12V; Value1: 1; IdsMax_A: -390mA; ChType: P; SizeAreaWB_mm2: 10.24; QgTyp_nC: -0.5; SizeArea_mm2: 4.84; SizeZ_mm: 1.1
Q11 Q13 = CMP-0000948-2: MOSFET, N-CH, 100 V, 0.17 A, SOT-323; Alternate Manufacturer: None; Manufacturer: Diodes Inc.; SizeZ_mm: 1.1; ChType: N; Value1: 1; VdsMax_V: 100V; SizeX_mm: 2.2; Vgs_V: 20V; Value: 100V; Rdson45_ohm: 10; SizeArea_mm2: 4.84; AEC Category: Q101; IdsMax_A: 170mA; SizeAreaWB_mm2: 10.24; U/M: EA
R257 = CMP-0026704-1: RES, 510, 1%, 0.1 W, 0402; Manufacturer: Panasonic; Power_W: 100mW; TempCo: 100 ppm/C; Value_Code: 510R; U/M: EA; Value: 510; SizeX_mm: 1; SizeY_mm: 0.5; SizeZ_mm: 0.6; Value2: 0.1W; VDC_V: 50V; AEC Category: Q200
R262-R264 R266 R267 R273 R277 R279 = CMP-0026680-1: RES, 220, 1%, 0.1 W, AEC-Q200 Grade 0, 0402; Manufacturer: Panasonic; Power_W: 100mW; TempCo: 100 ppm/C; Value_Code: 220R; U/M: EA; Value: 220; SizeX_mm: 1; SizeY_mm: 0.5; SizeZ_mm: 0.6; Value2: 0.1W; AEC Qualified: Y; VDC_V: 50V; AEC Grade: 0; AEC Category: Q200
R265 R302 R314 = CMP-0078194-1: as R259 on sheet PROC111_XDS110_2
R268-R271 R274-R276 = CMP-0026658-1: RES, 10.0 k, 1%, 0.1 W, 0402; Manufacturer: Panasonic; Power_W: 100mW; TempCo: 100 ppm/C; Value_Code: 10k0; U/M: EA; Value: 10.0k; EIA_Code: E96; Res_ohm: 10k; SizeX_mm: 1; SizeY_mm: 0.5; SizeZ_mm: 0.6; Value2: 0.1W; VDC_V: 50V; AEC Category: Q200
R272 R303 R317 = CMP-0078212-1: RES, 510, 5%, 0.1 W, AEC-Q200 Grade 0, 0402; Manufacturer: Panasonic; Value_Code: 510R; SizeArea_mm2: 0.5; AEC Qualified: Y; AEC Category: Q200; Value: 510; SizeZ_mm: 0.6; EIA_Code: E24; TempCo: 200 ppm/C; AEC Grade: 0; Power_W: 100mW; VDC_V: 50V; Value2: 0.1W; U/M: EA; SizeX_mm: 1
R278 R304 = CMP-0078193-1: RES, 1.0 k, 5%, 0.1 W, AEC-Q200 Grade 0, 0402; Manufacturer: Panasonic; Value_Code: 1k00; SizeArea_mm2: 0.5; AEC Qualified: Y; AEC Category: Q200; Res_ohm: 1k; Value: 1.0k; SizeZ_mm: 0.6; Green_REACh: Passed; EIA_Code: E24; TempCo: 200 ppm/C; AEC Grade: 0; Power_W: 100mW; VDC_V: 50V; Value2: 0.1W; Green_Lifecycle: Active; U/M: EA; SizeX_mm: 1
R313 R315 = CMP-0025998-3: RES, 130, 1%, 0.063 W, AEC-Q200 Grade 0, 0402; Manufacturer: Vishay-Dale; Power_W: 63mW; TempCo: 100 ppm/C; Value_Code: 130R; Value: 130; EIA_Code: E96; SizeX_mm: 1; SizeY_mm: 0.5; SizeZ_mm: 0.6; Value2: 0.063W; AEC Qualified: Y; VDC_V: 50V; AEC Category: Q200; AEC Grade: 0
U48 = CMP-0044782-1: 8-Bit LED Driver with I2C Interface, D0016A, TUBE; Manufacturer: Texas Instruments; IO(PEAK)(A): 0.21; Priority (type 2): 1; rDS(on)(Ohms): 5; VDS(Max)(V): 40; IO(CONT)(A): 0.1; ICC(uA): 620; tPLH(ns): 1150; Rating: Catalog

## Sheet PROC111_Hardware.SchDoc
size 431 x 279 mm; Date: Not shown in title block; ApprovedBy: Not shown in title block; CheckedBy: Not shown in title block; Author: Not shown in title block; CompanyName: Not shown in title block; Engineer: Not shown in title block; Organization: Not shown in title block; Address1: Not shown in title block; Address2: Not shown in title block; Address3: Not shown in title block; Address4: Not shown in title block; DocumentNumber: 24; Revision: Use project parameter SCH_Rev; SheetNumber: 24; SheetTotal: 24; PageSetup: Record=PageOptions¦CenterHorizontal=True¦CenterVertical=True¦PrintScale=1.00¦XCorrection=1.00¦YCorrection=1.00¦PrintKind=0¦BorderSize=5000000¦LeftOffset=0¦BottomOffset=0¦Orientation=2¦PaperLength=1000¦PaperWidth=1000¦Scale=100¦PaperSource=15¦PrintQuality=600¦MediaType=1¦DitherType=10¦PaperKind=Letter¦PrintScaleMode=1
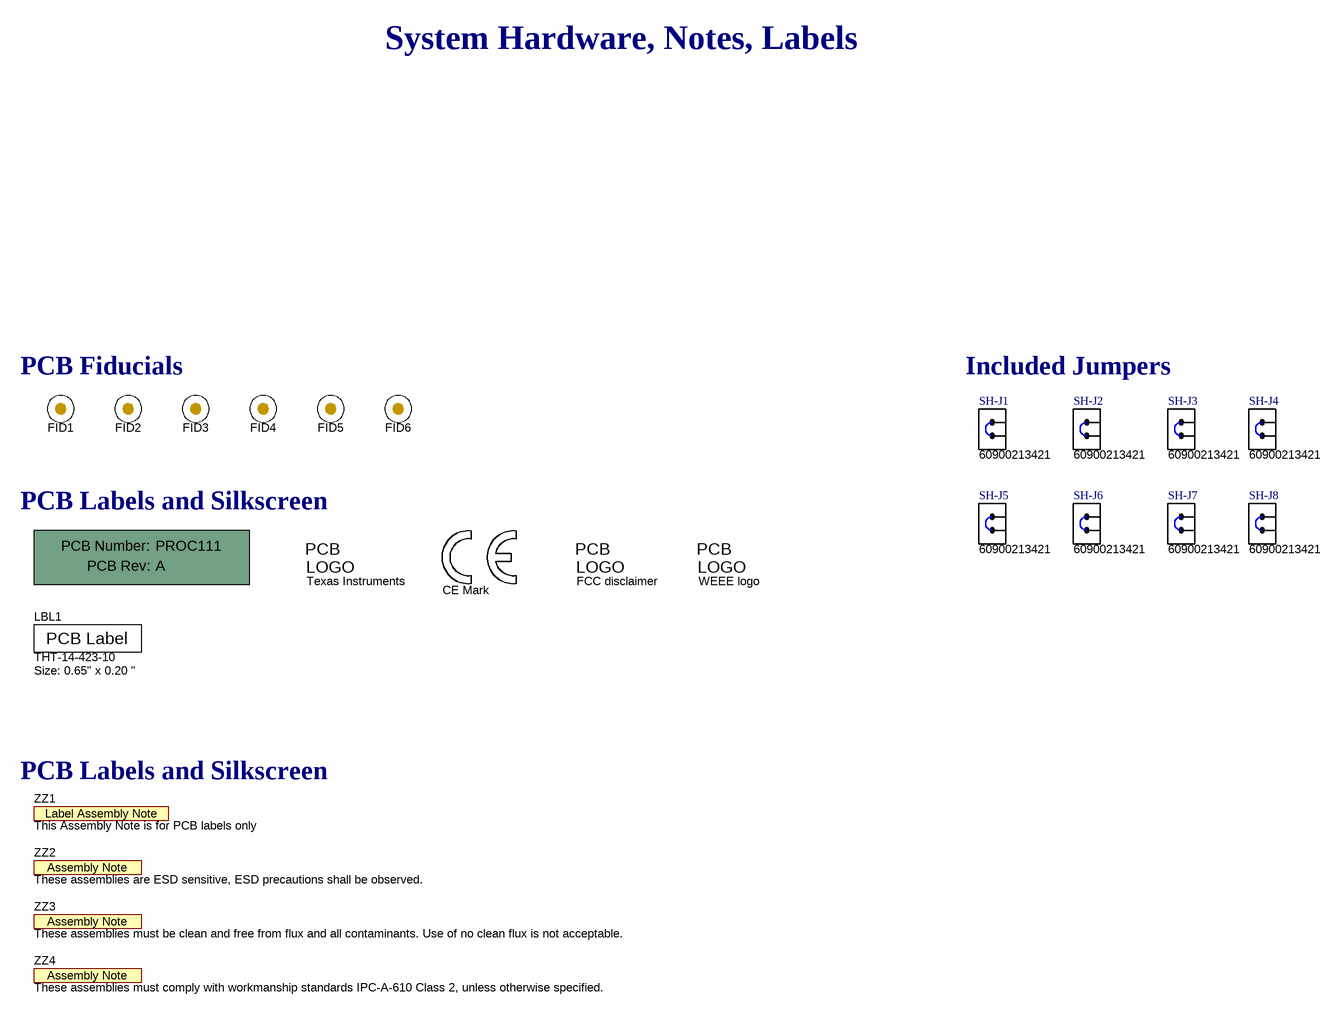
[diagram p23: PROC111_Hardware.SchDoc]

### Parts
!PCB1  Printed Circuit Board  (value not drawn)  (mechanical)
FID1  Fiducial  [Fiducial10-20]  (value not drawn)  (no BOM)
FID2  Fiducial  [Fiducial10-20]  (value not drawn)  (no BOM)
FID3  Fiducial  [Fiducial10-20]  (value not drawn)  (no BOM)
FID4  Fiducial  [Fiducial10-20]  (value not drawn)  (no BOM)
FID5  Fiducial  [Fiducial10-20]  (value not drawn)  (no BOM)
FID6  Fiducial  [Fiducial10-20]  (value not drawn)  (no BOM)
LBL1  THT-14-423-10  Note: Size: 0.65" x 0.20 "  [Label_650x200]
Logo1  CE Mark  [CE_Mark_5mm]  (no BOM)
Logo2  Texas Instruments  [TI_Stacked_Overlay_Small]  (no BOM)
Logo3  FCC disclaimer  [FCC_disclaimer]  (no BOM)
Logo4  WEEE logo  [WEEE_Minimum]  (no BOM)
SH-J1  60900213421  [Wurth_60900213421]
SH-J2  60900213421  [Wurth_60900213421]
SH-J3  60900213421  [Wurth_60900213421]
SH-J4  60900213421  [Wurth_60900213421]
SH-J5  60900213421  [Wurth_60900213421]
SH-J6  60900213421  [Wurth_60900213421]
SH-J7  60900213421  [Wurth_60900213421]
SH-J8  60900213421  [Wurth_60900213421]
ZZ1  This Assembly Note is for PCB labels only  [AssemblyNoteLabel]  (no BOM)
ZZ2  These assemblies are ESD sensitive, ESD precautions shall be observed.  [AssemblyNote]  (no BOM)
ZZ3  These assemblies must be clean and free from flux and all contaminants. Use of no clean flux is not acceptable.  [AssemblyNote]  (no BOM)
ZZ4  These assemblies must comply with workmanship standards IPC-A-610 Class 2, unless otherwise specified.  [AssemblyNote]  (no BOM)

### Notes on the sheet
- System Hardware, Notes, Labels
- PCB Fiducials
- Included Jumpers
- PCB Labels and Silkscreen
- (near ZZ1) PCB Labels and Silkscreen

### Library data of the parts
!PCB1 = CMP-0003618-2: Manufacturer: Any; PartNumber: PROC111
FID1-FID6 = CMP-0077181-1: Fiducial mark.  There is nothing to buy or mount.
LBL1 = CMP-0003625-1: Thermal Transfer Printable Labels, 0.650" W x 0.200" H - 10,000 per roll; Manufacturer: Brady; CompType: Label
Logo1 = CMP-0074844-1: SymbolCreator: a0412235
Logo2 = CMP-0074838-1: Texas Instrument Corporate Signature; SymbolCreator: a0412235; Lib Reference: TI_Logo; Library Reference: Logo
Logo3 = CMP-0074847-1: FCC_disclaimer; Library Reference: Logo
Logo4 = CMP-0074769-1
SH-J1-SH-J8 = CMP-0003761-2: Shunt, 2.54mm, Gold, Black; Manufacturer: Wurth Elektronik
ZZ1 = CMP-0003616-3
ZZ2 = CMP-0077236-1
ZZ3 = CMP-0077237-1
ZZ4 = CMP-0077238-1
